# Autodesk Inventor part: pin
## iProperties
Created: 2007-01
Part Number: pin
Cost Center: 0 kg
Material: S235JRG2 (1.0038)
Document SubType Name: Modeling
Designer: M. Fiedler
Manufacturer: Standard
Standards Organization: Custom
Einheit: Stück
Ersatzteil: ET AB VT
Grundoberfläche: Rz6.3
WSK a+: 0
WSK a-: -0.1
WSK i+: +0.1
WSK i-: 0
SaveDate: 2007-01-24
SaveTime: 22:43
FileName: pin
Masse: 0 kg
Author: M. Fiedler
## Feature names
1. Drehung1 [Revolution]
